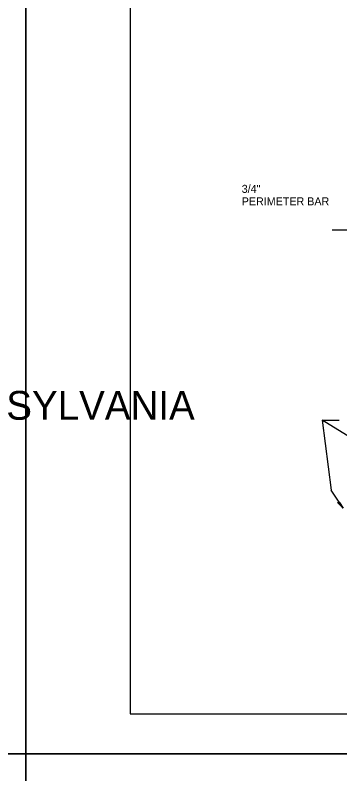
# Model space of a CAD drawing. Extents: x 2087776 to 2104538, y 970919 to 982612.
# Drawn here: x 2096040 to 2096439, y 978690 to 979622 of the extents above; entities that cross this region are included whole.
import ezdxf

# ---------------------------------------------------------------- set-up
doc = ezdxf.new("R2010")
doc.units = 0
doc.layers.add('1', color=7, linetype='Continuous')
doc.layers.add('PLT-BNDY', color=7, linetype='Continuous')

msp = doc.modelspace()

# ---------------------------------------------------------------- linework, layer by layer
at = {"layer": '1'}
for p, q in [((2096895.26, 979358.31), (2096429.28, 979358.31)), ((2096416.67, 979124.46), (2096437.53, 979124.46)), ((2096416.67, 979124.46), (2096428.07, 979038.59))]:
    msp.add_line(p, q, dxfattribs=at)
for points in [[(2098759.93, 978763.82), (2098759.93, 980614.22), (2096181.19, 980614.22), (2096181.19, 978763.82), (2098759.93, 978763.82), (2098759.93, 978850.3), (2098103.76, 978850.3), (2098103.76, 979062.5), (2098759.93, 979062.5), (2098759.93, 979157.53), (2098103.76, 979157.53), (2098103.76, 978763.82), (2098362.29, 978763.82), (2098362.29, 978850.3), (2098362.29, 978763.82), (2098614.92, 978763.82), (2098614.92, 978850.3), (2098614.92, 978809.9), (2098759.93, 978809.9)], [(2096481.79, 979084.5), (2096416.67, 979124.46)], [(2096442.75, 979016.46), (2096428.07, 979038.59)], [(2096442.75, 979016.46), (2096435.81, 979023.6), (2096436.24, 979023.43), (2096436.67, 979023.26), (2096437.05, 979023.28), (2096437.43, 979023.3), (2096437.73, 979023.43), (2096438.04, 979023.56), (2096438.28, 979023.79), (2096438.52, 979024.02)], [(2096442.75, 979016.46), (2096438.28, 979023.79), (2096438.04, 979023.56), (2096442.75, 979016.46), (2096437.73, 979023.43), (2096437.43, 979023.3), (2096442.75, 979016.46), (2096437.05, 979023.28), (2096436.67, 979023.26), (2096442.75, 979016.46), (2096436.24, 979023.43)]]:
    msp.add_lwpolyline(points, dxfattribs=at)
at = {"layer": 'PLT-BNDY'}
for points in [[(2093294.05, 980663.43), (2096053.23, 980663.43), (2096053.23, 978714.61), (2093294.05, 978714.61)], [(2096053.23, 980663.43), (2098812.42, 980663.43), (2098812.42, 978714.61), (2096053.23, 978714.61)], [(2093294.05, 978714.61), (2096053.23, 978714.61), (2096053.23, 976765.79), (2093294.05, 976765.79)], [(2096053.23, 978714.61), (2098812.42, 978714.61), (2098812.42, 976765.79), (2096053.23, 976765.79)]]:
    msp.add_lwpolyline(points, close=True, dxfattribs=at)

# ---------------------------------------------------------------- texts
at = {"layer": '1'}
for s, height, p in [('3/4"', 9.843, (2096318.08, 979404.02)), ('PERIMETER BAR', 9.8425, (2096318.08, 979388.66)), ('COMMONWEALTH OF PENNSYLVANIA', 35.3785, (2095387.72, 979125.19))]:
    msp.add_text(s, height=height, dxfattribs=at).set_placement(p)

doc.saveas('drawing.dxf')
